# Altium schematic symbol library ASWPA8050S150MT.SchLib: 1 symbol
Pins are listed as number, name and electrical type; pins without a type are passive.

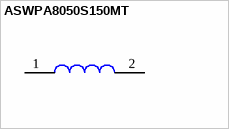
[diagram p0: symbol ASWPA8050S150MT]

## ASWPA8050S150MT
designator L?
Manufacturer: Sunlord; CompType: Inductor; Value: 15uH
footprint ASWPA8050S150MT
pins: 1, 2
